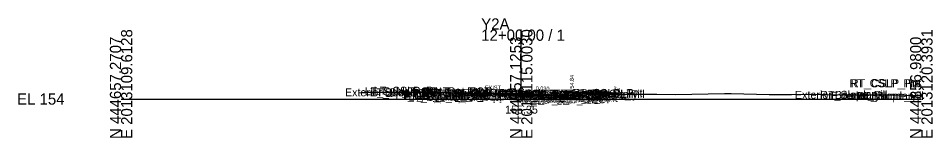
# Model space of a CAD drawing. Extents: x -26 to 203, y -10 to 5517.
# Drawn here: x -25.7 to 202.8, y 3990.3 to 4020.2 of the extents above; entities that cross this region are included whole.
import ezdxf

# ---------------------------------------------------------------- set-up
doc = ezdxf.new("R2010")
doc.units = 0
for name, color, linetype in [('Default', 7, 'Continuous'), ('Exist Cross Section Cell', 7, 'Continuous'), ('Exist XS Center Line Elevation Label', 7, 'Continuous'), ('Exist XS Ground Line', 7, 'Continuous'), ('Prop CMT Conc Surface', 7, 'Continuous'), ('Prop CMT Concrete Structures', 7, 'Continuous'), ('Prop CMT Pvmt Course 1', 7, 'Continuous'), ('Prop CMT Pvmt Course 1 CG', 7, 'Continuous'), ('Prop CMT Pvmt Course 1 Wedge', 7, 'Continuous'), ('Prop CMT Pvmt Course 2', 7, 'Continuous'), ('Prop CMT Pvmt Course 2 Wedge', 7, 'Continuous'), ('Prop CMT Pvmt Course 3', 7, 'Continuous'), ('Prop CMT Pvmt Course 3 Wedge', 7, 'Continuous'), ('Prop CMT Pvmt Surface', 7, 'Continuous'), ('Prop CMT Pvmt Wedge Surface 1', 7, 'Continuous'), ('Prop CMT Pvmt Wedge Surface 2', 7, 'Continuous'), ('Prop CMT Pvmt Wedge Surface 3', 7, 'Continuous'), ('Prop CMT Slope Grass', 7, 'Continuous'), ('Prop CMT Subgrade Earthwork', 7, 'Continuous'), ('Prop XS Earthwork Shape', 7, 'Continuous'), ('Prop XS Hydro Elevations', 7, 'Continuous'), ('Prop XS SE Text', 7, 'Continuous'), ('Prop XS Side Slope Text', 7, 'Continuous'), ('Scratch_Level_0', 7, 'Continuous')]:
    doc.layers.add(name, color=color, linetype=linetype)

msp = doc.modelspace()

# ---------------------------------------------------------------- linework, layer by layer
at = {"layer": 'Exist Cross Section Cell'}
for p, q in [((100, 4000), (100, 4017.39)), ((0, 4000), (100, 4000)), ((100, 4000), (200, 4000))]:
    msp.add_line(p, q, dxfattribs=at)
at = {"layer": 'Exist XS Ground Line'}
msp.add_lwpolyline([(59.31, 4001.56), (60.78, 4001.7), (61.54, 4001.75), (66.97, 4001.69), (71.55, 4001.68), (76.47, 4001.67), (81.57, 4001.62), (87.27, 4001.53), (92.76, 4001.45), (100, 4001.35), (100.98, 4001.34), (101.94, 4001.32), (102.77, 4001.31), (109.14, 4001.03), (113.97, 4000.82), (115.09, 4000.75), (115.77, 4000.72), (116.28, 4001.22), (119.01, 4001.22), (120.83, 4001.22), (122.57, 4001.22), (126.77, 4001.24), (129.92, 4001.24), (133.86, 4001.18), (138.57, 4001.16), (150.77, 4001.38), (151.68, 4001.39), (152.49, 4001.37), (161.99, 4001.14), (167.53, 4001.16), (171.71, 4001.18), (181, 4001.08), (181.73, 4001.07), (190.5, 4001.05), (191.74, 4001.04), (200, 4000.86)], dxfattribs=at)
at = {"layer": 'Prop CMT Conc Surface'}
for points in [[(110.65, 4000.98), (112.65, 4000.84)], [(112.65, 4000.84), (112.65, 4001.34), (113.15, 4001.34)]]:
    msp.add_lwpolyline(points, dxfattribs=at)
at = {"layer": 'Prop CMT Concrete Structures'}
for points in [[(110.65, 4000.98), (112.65, 4000.84), (112.65, 4001.34), (113.15, 4001.34)], [(113.15, 4001.34), (113.15, 4000.32), (110.65, 4000.39)], [(110.65, 4000.39), (110.65, 4000.98)], [(122.15, 4001.53), (116.82, 4001.42)], [(116.82, 4001.42), (116.82, 4001.09)], [(116.82, 4001.09), (122.15, 4001.19)], [(122.15, 4001.19), (122.15, 4001.53)]]:
    msp.add_lwpolyline(points, dxfattribs=at)
at = {"layer": 'Prop CMT Pvmt Course 1'}
for points in [[(100, 4001.3), (86, 4001.44)], [(86, 4001.19), (86, 4001.44)], [(86, 4001.31), (100, 4001.17)], [(100, 4001.05), (100, 4001.3)], [(100, 4001.3), (110.65, 4000.98)], [(100, 4001.05), (100, 4001.3)], [(100, 4001.17), (100, 4001.05), (100, 4001.05)], [(109.63, 4000.88), (100, 4001.17)], [(100, 4001.17), (100, 4001.05), (100, 4001.05)], [(109.63, 4000.76), (109.63, 4000.88)], [(110.65, 4000.73), (109.63, 4000.76)], [(110.65, 4000.98), (110.65, 4000.73)]]:
    msp.add_lwpolyline(points, dxfattribs=at)
at = {"layer": 'Prop CMT Pvmt Course 1 CG'}
for points in [[(110.65, 4000.39), (113.65, 4000.3), (113.99, 3999.96)], [(110.65, 4000.06), (110.65, 4000.39)], [(113.99, 3999.96), (110.65, 4000.06)]]:
    msp.add_lwpolyline(points, dxfattribs=at)
at = {"layer": 'Prop CMT Pvmt Course 1 Wedge'}
for points in [[(100, 4001.17), (86, 4001.31)], [(100, 4001.17), (109.63, 4000.88)]]:
    msp.add_lwpolyline(points, dxfattribs=at)
at = {"layer": 'Prop CMT Pvmt Course 2'}
for points in [[(86, 4000.85), (86, 4001.19)], [(109.63, 4000.42), (109.63, 4000.76)], [(109.63, 4000.76), (110.65, 4000.73)], [(110.65, 4000.39), (109.63, 4000.42)], [(110.65, 4000.73), (110.65, 4000.39)]]:
    msp.add_lwpolyline(points, dxfattribs=at)
at = {"layer": 'Prop CMT Pvmt Course 2 Wedge'}
for points in [[(100, 4001.05), (86, 4001.19)], [(100, 4001.05), (109.63, 4000.76)]]:
    msp.add_lwpolyline(points, dxfattribs=at)
at = {"layer": 'Prop CMT Pvmt Course 3'}
for points in [[(109.63, 4000.42), (110.65, 4000.39)], [(109.63, 4000.09), (109.63, 4000.42)], [(110.65, 4000.06), (109.63, 4000.09)], [(110.65, 4000.39), (110.65, 4000.06)]]:
    msp.add_lwpolyline(points, dxfattribs=at)
at = {"layer": 'Prop CMT Pvmt Course 3 Wedge'}
for points in [[(100, 4000.71), (86, 4000.85)], [(100, 4000.71), (109.63, 4000.42)]]:
    msp.add_lwpolyline(points, dxfattribs=at)
at = {"layer": 'Prop CMT Pvmt Surface'}
for points in [[(100, 4001.3), (86, 4001.44)], [(100, 4001.3), (110.65, 4000.98)]]:
    msp.add_lwpolyline(points, dxfattribs=at)
at = {"layer": 'Prop CMT Pvmt Wedge Surface 1'}
for points in [[(86, 4001.44), (86, 4001.19)], [(100, 4001.17), (86, 4001.31)], [(100, 4001.17), (109.63, 4000.88)], [(109.63, 4000.88), (109.63, 4000.76)], [(109.63, 4000.76), (110.65, 4000.73)], [(110.65, 4000.73), (110.65, 4000.98)]]:
    msp.add_lwpolyline(points, dxfattribs=at)
at = {"layer": 'Prop CMT Pvmt Wedge Surface 2'}
for points in [[(100, 4001.05), (86, 4001.19)], [(100, 4001.05), (110.65, 4000.73)], [(110.65, 4000.73), (110.65, 4000.98)]]:
    msp.add_lwpolyline(points, dxfattribs=at)
at = {"layer": 'Prop CMT Pvmt Wedge Surface 3'}
for points in [[(100, 4000.71), (86, 4000.85)], [(100, 4000.71), (110.65, 4000.39)], [(110.65, 4000.39), (110.65, 4000.98)]]:
    msp.add_lwpolyline(points, dxfattribs=at)
at = {"layer": 'Prop CMT Slope Grass'}
msp.add_lwpolyline([(113.15, 4001.34), (122.65, 4001.53), (123.56, 4001.22)], dxfattribs=at)
at = {"layer": 'Prop CMT Subgrade Earthwork'}
msp.add_line((86, 4001.44), (86, 4001.55), dxfattribs=at)
for points in [[(109.63, 4000.09), (109.61, 4001.01)], [(109.63, 4000.09), (110.65, 4000.06)], [(110.65, 4000.06), (113.99, 3999.96), (115.41, 4001.38)]]:
    msp.add_lwpolyline(points, dxfattribs=at)
at = {"layer": 'Prop XS Earthwork Shape'}
for points in [[(87.27, 4001.53), (92.76, 4001.45), (100, 4001.35), (100.98, 4001.34), (101.94, 4001.32), (102.77, 4001.31), (109.14, 4001.03), (109.61, 4001.01), (100, 4001.3), (86, 4001.44), (86, 4001.55)], [(109.61, 4001.01), (110.65, 4000.96), (110.65, 4000.39), (113.15, 4000.32), (113.15, 4000.85), (113.97, 4000.82), (114.8, 4000.77), (113.99, 3999.96), (110.65, 4000.06), (109.63, 4000.09)], [(110.65, 4000.39), (110.65, 4000.96), (111.15, 4000.94), (112.65, 4000.84), (112.65, 4000.88), (113.15, 4000.85), (113.15, 4000.32)], [(111.15, 4000.94), (112.65, 4000.88), (112.65, 4000.84)], [(114.8, 4000.77), (115.09, 4000.75), (115.77, 4000.72), (116.28, 4001.22), (116.82, 4001.22), (116.82, 4001.42), (115.41, 4001.38)], [(116.82, 4001.09), (122.15, 4001.19), (122.15, 4001.22), (120.83, 4001.22), (119.01, 4001.22), (116.82, 4001.22)], [(122.65, 4001.53), (123.56, 4001.22), (122.57, 4001.22), (122.15, 4001.22), (122.15, 4001.53)]]:
    msp.add_lwpolyline(points, close=True, dxfattribs=at)

# ---------------------------------------------------------------- texts
at = {"layer": 'Default'}
msp.add_text('-', height=0.0001, dxfattribs=at).set_placement((0, 4000))
at = {"layer": 'Exist Cross Section Cell'}
for s, p in [('Y2A', (90, 4017.39)), ('12+00.00 / 1', (90, 4014.59)), ('EL 154', (-26, 3998.6))]:
    msp.add_text(s, height=2.8, dxfattribs=at).set_placement(p)
for s, p in [('N 444657.2707', (0, 3990)), ('E 2013109.6128', (2.8, 3990)), ('N 444757.1253', (100, 3990)), ('E 2013115.0030', (102.8, 3990)), ('N 444856.9800', (200, 3990)), ('E 2013120.3931', (202.8, 3990))]:
    msp.add_text(s, height=2.8, rotation=90, dxfattribs=at).set_placement(p)
at = {"layer": 'Exist XS Center Line Elevation Label'}
msp.add_text('155.35', height=2, dxfattribs=at).set_placement((95.98, 3996.35))
at = {"layer": 'Prop XS Hydro Elevations'}
msp.add_text('154.84', height=1, rotation=90, dxfattribs=at).set_placement((113.15, 4001.84))
at = {"layer": 'Prop XS SE Text'}
for s, rotation, p in [('EXIST', 359.4271, (90.94, 4002.39)), ('0.030', 358.2816, (103.6, 4002.19))]:
    msp.add_text(s, height=1, rotation=rotation, dxfattribs=at).set_placement(p)
at = {"layer": 'Prop XS Side Slope Text'}
msp.add_text('3:1', height=1, rotation=341.5668, dxfattribs=at).set_placement((122.85, 4002.26))
at = {"layer": 'Scratch_Level_0'}
for s, p in [('RT_CSLP_Pnt', (182.04, 4002.97)), ('RT_CSLP_Pnt', (182.4, 4002.97)), ('Exterior Boundary', (55.95, 4000.68)), ('LT_Sub_Trench_Out_DLT', (60.87, 4000.93)), ('LT_Slope_Fill', (62.33, 4000.68)), ('LT_CSLP_Pnt', (63.17, 4001.08)), ('LT_CG1_Shelf_Out', (68.55, 3999.89)), ('LT_CG_Top_Face', (70.26, 4000.89)), ('LT_CG_Top_BOC', (70.78, 4000.89)), ('LT_CG_Bot_BOC', (70.81, 3999.89)), ('LT_PV_Sub_Tie_Out', (70.96, 4000.55)), ('LT_CG_Top_Gut', (71.24, 4000.39)), ('LT_Sub_OEOP', (71.78, 3999.56)), ('LT_PV_OEEOP_EG', (73.54, 4000.55)), ('LT_CG_Bot_IE', (74.91, 3999.86)), ('LT_Sub_OEOT', (75.08, 3999.53)), ('LT_PV2_OEOT', (75.17, 4000.2)), ('LT_PV3_OEOT', (75.17, 3999.86)), ('LT_Sub_OEEOP', (75.21, 3999.52)), ('LT_PV2_OEEOP', (75.31, 4000.19)), ('LT_PV3_OEEOP', (75.31, 3999.85)), ('LT_PV1_OEOT', (75.74, 4000.45)), ('LT_PV1_OEEOP', (75.87, 4000.31)), ('RT_PV_IEEOP_EG', (88.14, 4000.35)), ('LT_PV_IEEOP_EG', (88.19, 4000.35)), ('RT_PV2_IEEOP', (89.91, 4000.05)), ('RT_PV3_IEEOP', (89.91, 3999.71)), ('LT_PV2_IEEOP', (89.95, 4000.05)), ('LT_PV3_IEEOP', (89.95, 3999.71)), ('RT_PV1_IEEOP', (90.47, 4000.17)), ('LT_PV1_IEEOP', (90.52, 4000.17)), ('PV2_PGL', (93.91, 4000.05)), ('PV1_PGL', (94.47, 4000.3)), ('RT_PV_Sub_Tie_Out', (94.51, 4000.01)), ('RT_Sub_Trench_Out_DLT', (95.93, 4000.38)), ('RT_PV_OEEOP_EG', (97.13, 4000.01)), ('RT_PV2_OEEOP', (98.89, 3999.76)), ('RT_PV1_OEEOP', (99.46, 3999.88)), ('RT_CG_Top_Face', (99.86, 4000.34)), ('RT_PV2_OEOT', (100.77, 3999.73)), ('RT_CG_Top_Gut', (100.84, 3999.84)), ('RT_PV1_OEOT', (101.34, 3999.98)), ('RT_CG_Top_BOC', (101.39, 4000.34)), ('Exterior Boundary', (107.7, 4000.22)), ('RT_CSLP_Pnt', (112.77, 4000.53)), ('RT_Slope_Fill', (114.03, 4000.22)), ('Exterior Boundary', (168.41, 4000.05)), ('RT_Slope_Fill', (174.74, 4000.05)), ('Exterior Boundary', (177.45, 3999.8)), ('RT_Slope_Fill', (183.78, 3999.8)), ('RT_Sub_OEEOP', (98.79, 3999.09)), ('RT_PV3_OEEOP', (98.89, 3999.42)), ('RT_CG1_Shelf_Out', (100.15, 3999.3)), ('RT_CG_Bot_IE', (100.51, 3999.39)), ('RT_Sub_OEOT', (100.68, 3999.06)), ('RT_PV3_OEOT', (100.77, 3999.39)), ('RT_CG_Bot_BOC', (101.42, 3999.32)), ('RT_Sub_OEOP', (104.05, 3998.96))]:
    msp.add_text(s, height=2, dxfattribs=at).set_placement(p)

doc.saveas('drawing.dxf')
